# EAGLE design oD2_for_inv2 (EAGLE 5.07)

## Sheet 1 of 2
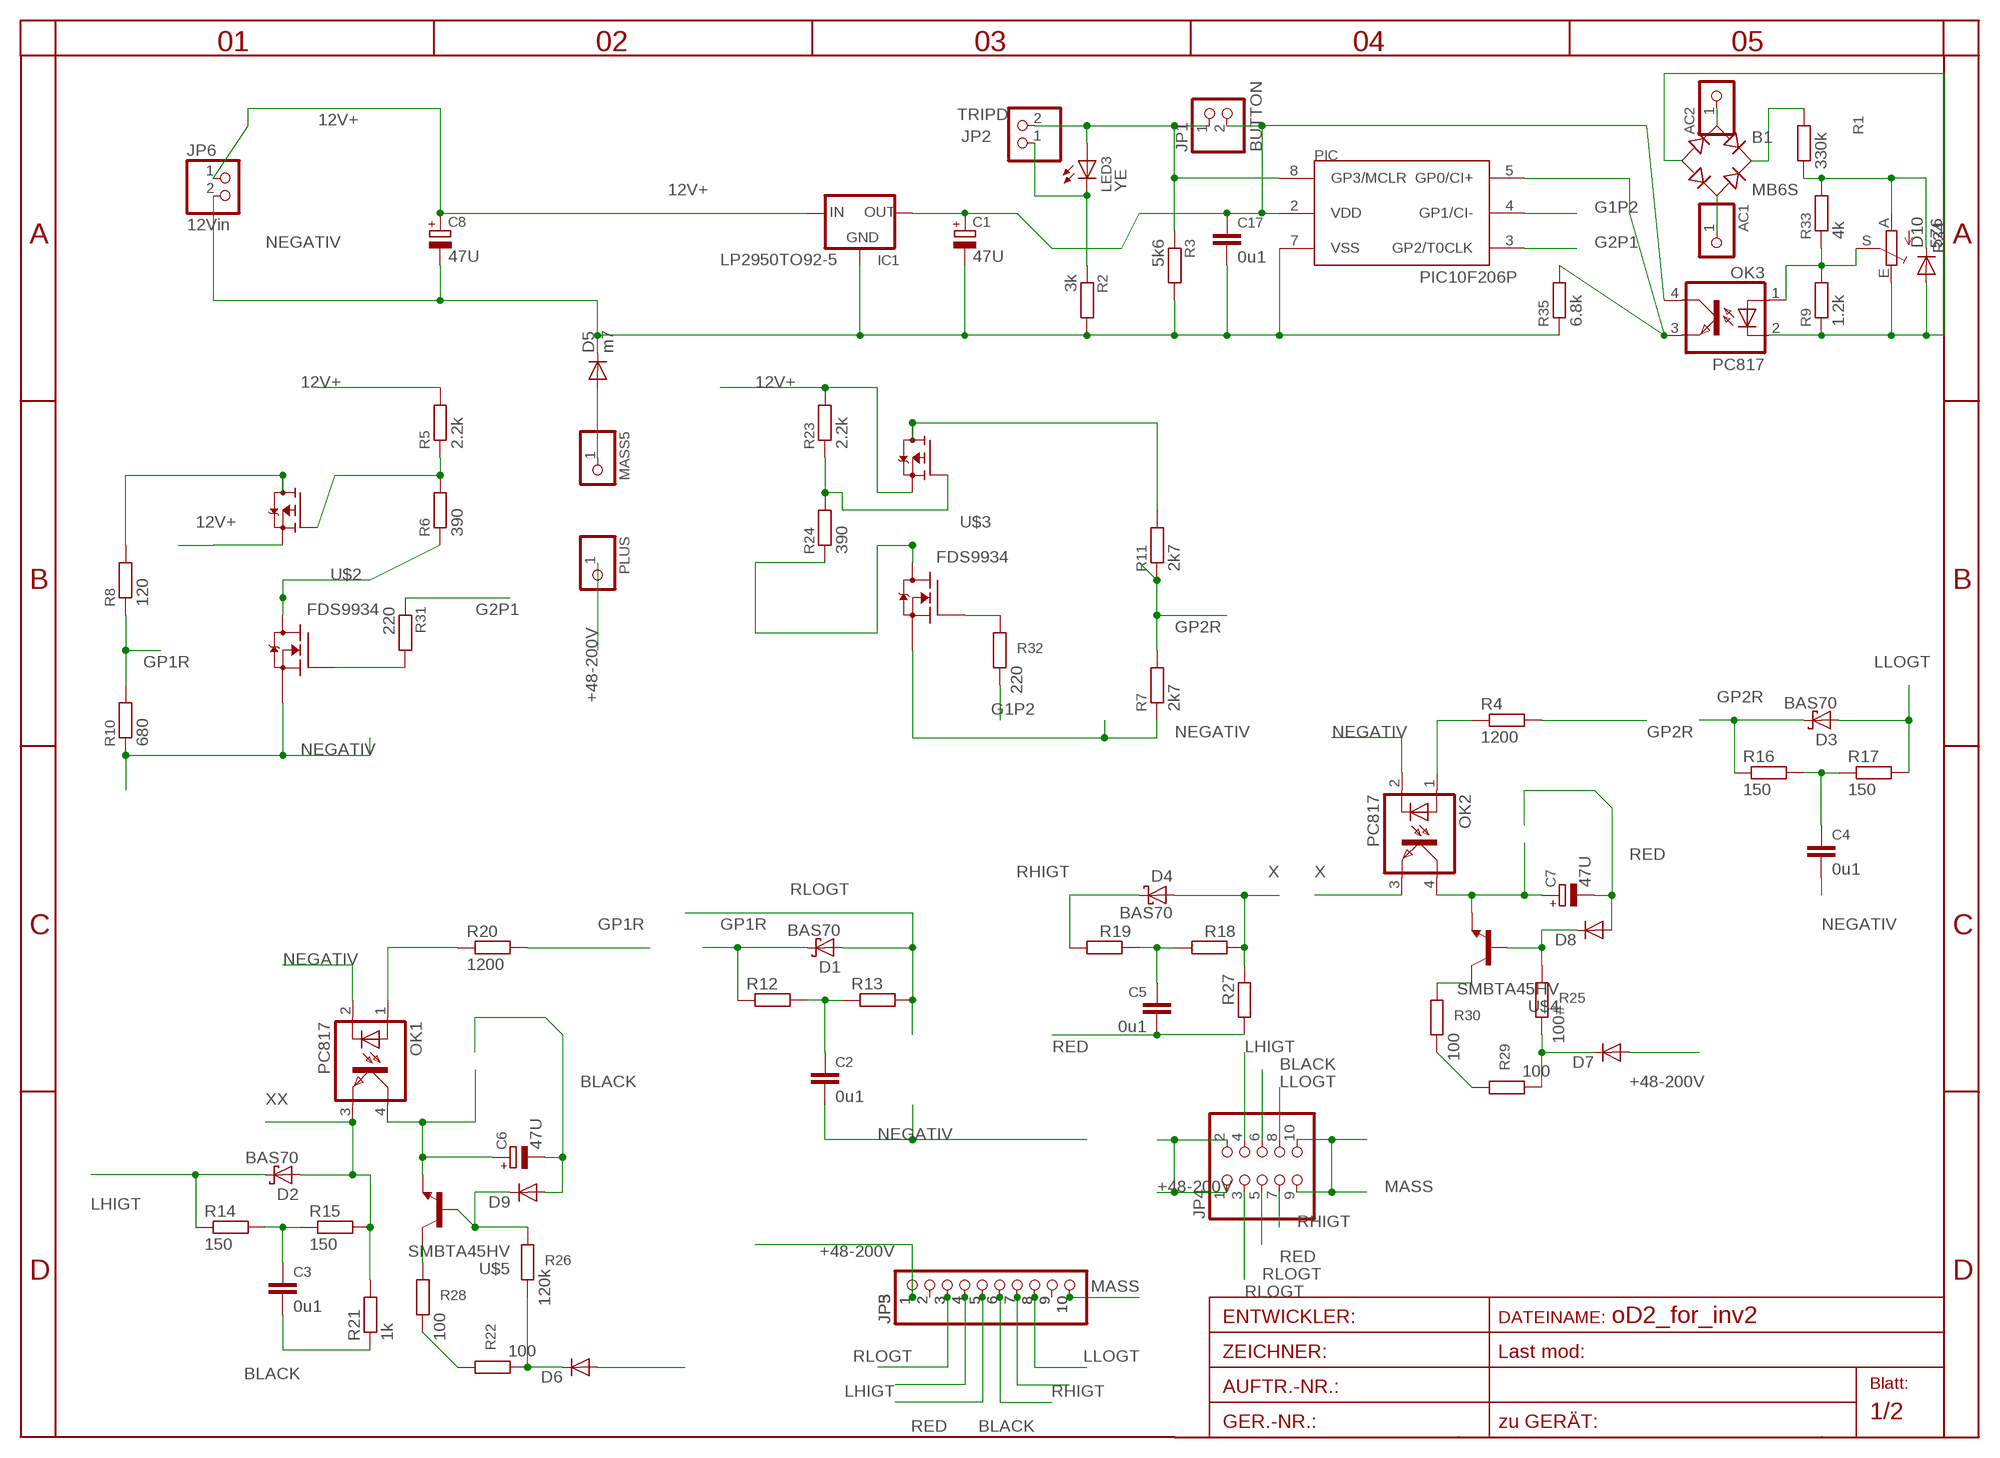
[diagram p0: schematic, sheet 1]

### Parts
AC1  PINHD-1X11MM6  [1X1MM8]
AC2  PINHD-1X11MM6  [1X1MM8]
B1  MB6S  [SOIC-4]
C1  47U  CPOL-EUE2.5-5  [E2,5-5]
C2  0u1  C-EUC1206  [C1206]
C3  0u1  C-EUC0805  [C0805]
C4  0u1  C-EUC1206  [C1206]
C5  0u1  C-EUC0805  [C0805]
C6  47U  CPOL-EUE2.5-6  [E2,5-6]
C7  47U  CPOL-EUE2.5-6  [E2,5-6]
C8  47U  CPOL-EUE2.5-7  [E2,5-7]
C17  0u1  C-EUC1206  [C1206]
D1  BAS70  [SOT23]
D2  BAS70  [SOT23]
D3  BAS70  [SOT23]
D4  BAS70  [SOT23]
D5  m7  DIODE-SMA-DO214  [SMA-DO214AC]
D6  DIODE-SMA-DO214  [SMA-DO214AC]
D7  DIODE-SMA-DO214  [SMA-DO214AC]
D8  DIODE-MINIMELF  [MINIMELF]
D9  DIODE-MINIMELF  [MINIMELF]
D10  5Z6  DIODE-MINIMELF  [MINIMELF]
IC1  LP2950TO92-5  [T092-5]
JP1  BUTTON  PINHD-1X2/90  [1X02/90]
JP2  TRIPD  PINHD-1X2/90  [1X02/90]
JP3  PINHD-1X10  [1X10WIDE]
JP4  PINHD-2X5  [2X05]
JP5  PINHD-1X10  [1X10WIDE]
JP6  12Vin  PINHD-1X2STR  [1X02]
LED3  YE  LEDCHIPLED_1206  [CHIPLED_1206]
MASS5  PINHD-1X11MM6  [1X1MM8]
OK1  PC817  [DIL04]
OK2  PC817  [DIL04]
OK3  PC817  [DIL04]
PIC  PIC10F206P  [DIL8]
PLUS  PINHD-1X11MM6  [1X1MM8]
R1  330k  R-EU_0204/5  [0204/5]
R2  3k  R-EU_R0805  [R0805]
R3  5k6  R-EU_R0805  [R0805]
R4  1200  R-EU_R1206  [R1206]
R5  2.2k  R-EU_R0805  [R0805]
R6  390  R-EU_R0805  [R0805]
R7  2k7  R-EU_R0805  [R0805]
R8  120  R-EU_R0805  [R0805]
R9  1.2k  R-EU_R0805  [R0805]
R10  680  R-EU_R0805  [R0805]
R11  2k7  R-EU_R0805  [R0805]
R12  R-EU_R0805  [R0805]
R13  R-EU_R0805  [R0805]
R14  150  R-EU_R0805  [R0805]
R15  150  R-EU_R0805  [R0805]
R16  150  R-EU_R0805  [R0805]
R17  150  R-EU_R0805  [R0805]
R18  R-EU_R0805  [R0805]
R19  R-EU_R0805  [R0805]
R20  1200  R-EU_R1206  [R1206]
R21  1k  R-EU_R0805  [R0805]
R22  100  R-EU_R1206  [R1206]
R23  2.2k  R-EU_R0805  [R0805]
R24  390  R-EU_R0805  [R0805]
R25  100#  R-EU_R1206  [R1206]
R26  120k  R-EU_R1206  [R1206]
R27  R-EU_R0805  [R0805]
R28  100  R-EU_R1206  [R1206]
R29  100  R-EU_R1206  [R1206]
R30  100  R-EU_R1206  [R1206]
R31  220  R-EU_R1206  [R1206]
R32  220  R-EU_R1206  [R1206]
R33  4k  R-EU_R0805  [R0805]
R34  TRIM_EU-S64W  [S64W]
R35  6.8k  R-EU_R0805  [R0805]
U$2  FDS9934  [SO-8]
U$3  FDS9934  [SO-8]
U$4  SMBTA45HV  [SOT23HV]
U$5  SMBTA45HV  [SOT23HV]

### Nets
12V+: C8.+ IC1.3(IN) JP6.1 R5.2 R23.2 U$2.3(Q2S) U$3.3(Q2S)
+48-200V: D6.A D7.A JP3.1 JP4.1 JP4.2 JP5.1 PLUS.1
BLACK: C3.2 C6.- D9.A JP3.6 JP4.6 JP5.6 R21.1
G1P2: PIC.4(GP1/CI-) R32.1
G2P1: PIC.3(GP2/T0CLK) R31.1
GP1R: D1.3(C) R8.1 R10.2 R12.1 R20.2
GP2R: D3.3(C) R4.2 R7.2 R11.1 R16.1
GP3: JP1.1 JP2.2 LED3.A PIC.8(GP3/MCLR) R3.1
LHIGT: D2.3(C) JP3.4 JP4.4 JP5.4 R14.1
LLOGT: D3.1(A) JP3.8 JP4.8 JP5.8 R17.2
MASS: D5.A JP3.10 JP4.9 JP4.10 JP5.10 MASS5.1 ; also sheet 2
N$1: OK3.3(EMIT) PIC.5(GP0/CI+) R35.2
N$2: R32.2 U$3.2(Q1G)
N$3: C3.1 R14.2 R15.1
N$4: R5.1 R6.2 U$2.4(Q2G)
N$5: R11.2 U$3.5(Q2D2) U$3.6(Q2D)
N$6: R31.2 U$2.2(Q1G)
N$7: C6.+ OK1.4(COL) U$5.2(E)
N$8: C5.1 R18.2 R19.1
N$9: R24.1 U$3.7(Q1D2) U$3.8(Q1D1)
N$11: R6.1 U$2.7(Q1D2) U$2.8(Q1D1)
N$12: C2.1 R12.2 R13.1
N$13: OK2.1(A) R4.1
N$14: C7.+ OK2.4(COL) U$4.2(E)
N$15: JP2.1 LED3.C R2.1
N$16: C4.1 R16.2 R17.1
N$17: OK1.1(A) R20.1
N$20: D7.K(C) R25.1 R29.1
N$21: R8.2 U$2.5(Q2D2) U$2.6(Q2D)
N$22: R23.1 R24.2 U$3.4(Q2G)
N$23: D6.K(C) R22.1 R26.1
N$24: R28.2 U$5.3(C)
N$25: JP3.2 JP5.2
N$26: R22.2 R28.1
N$27: D9.C R26.2 U$5.1(B)
N$28: R29.2 R30.1
N$31: D8.C R25.2 U$4.1(B)
N$33: R30.2 U$4.3(C)
N$34: JP3.9 JP5.9
N$35: OK3.1(A) R9.2 R33.1 R34.S
N$36: D10.C R1.1 R33.2 R34.A
N$37: B1.- D10.A OK3.2(C) R9.1 R34.E
N$38: AC1.1 B1.~2(AC2)
N$39: AC2.1 B1.~1(AC1)
N$40: B1.+ R1.2
NEGATIV: C1.- C2.2 C4.2 C8.- C17.2 D5.K(C) IC1.2(GND) JP6.2 OK1.2(C) OK2.2(C) PIC.7(VSS) R2.2 R3.2 R7.1 R10.1 R35.1 U$2.1(Q1S) U$3.1(Q1S)
RED: C5.2 C7.- D8.A JP3.5 JP4.5 JP5.5 R27.2
RHIGT: D4.3(C) JP3.7 JP4.7 JP5.7 R19.2
RLOGT: D1.1(A) JP3.3 JP4.3 JP5.3 R13.2
VDD: C1.+ C17.1 IC1.1(OUT) JP1.2 OK3.4(COL) PIC.2(VDD)
X: D4.1(A) OK2.3(EMIT) R18.1 R27.1
XX: D2.1(A) OK1.3(EMIT) R15.2 R21.2

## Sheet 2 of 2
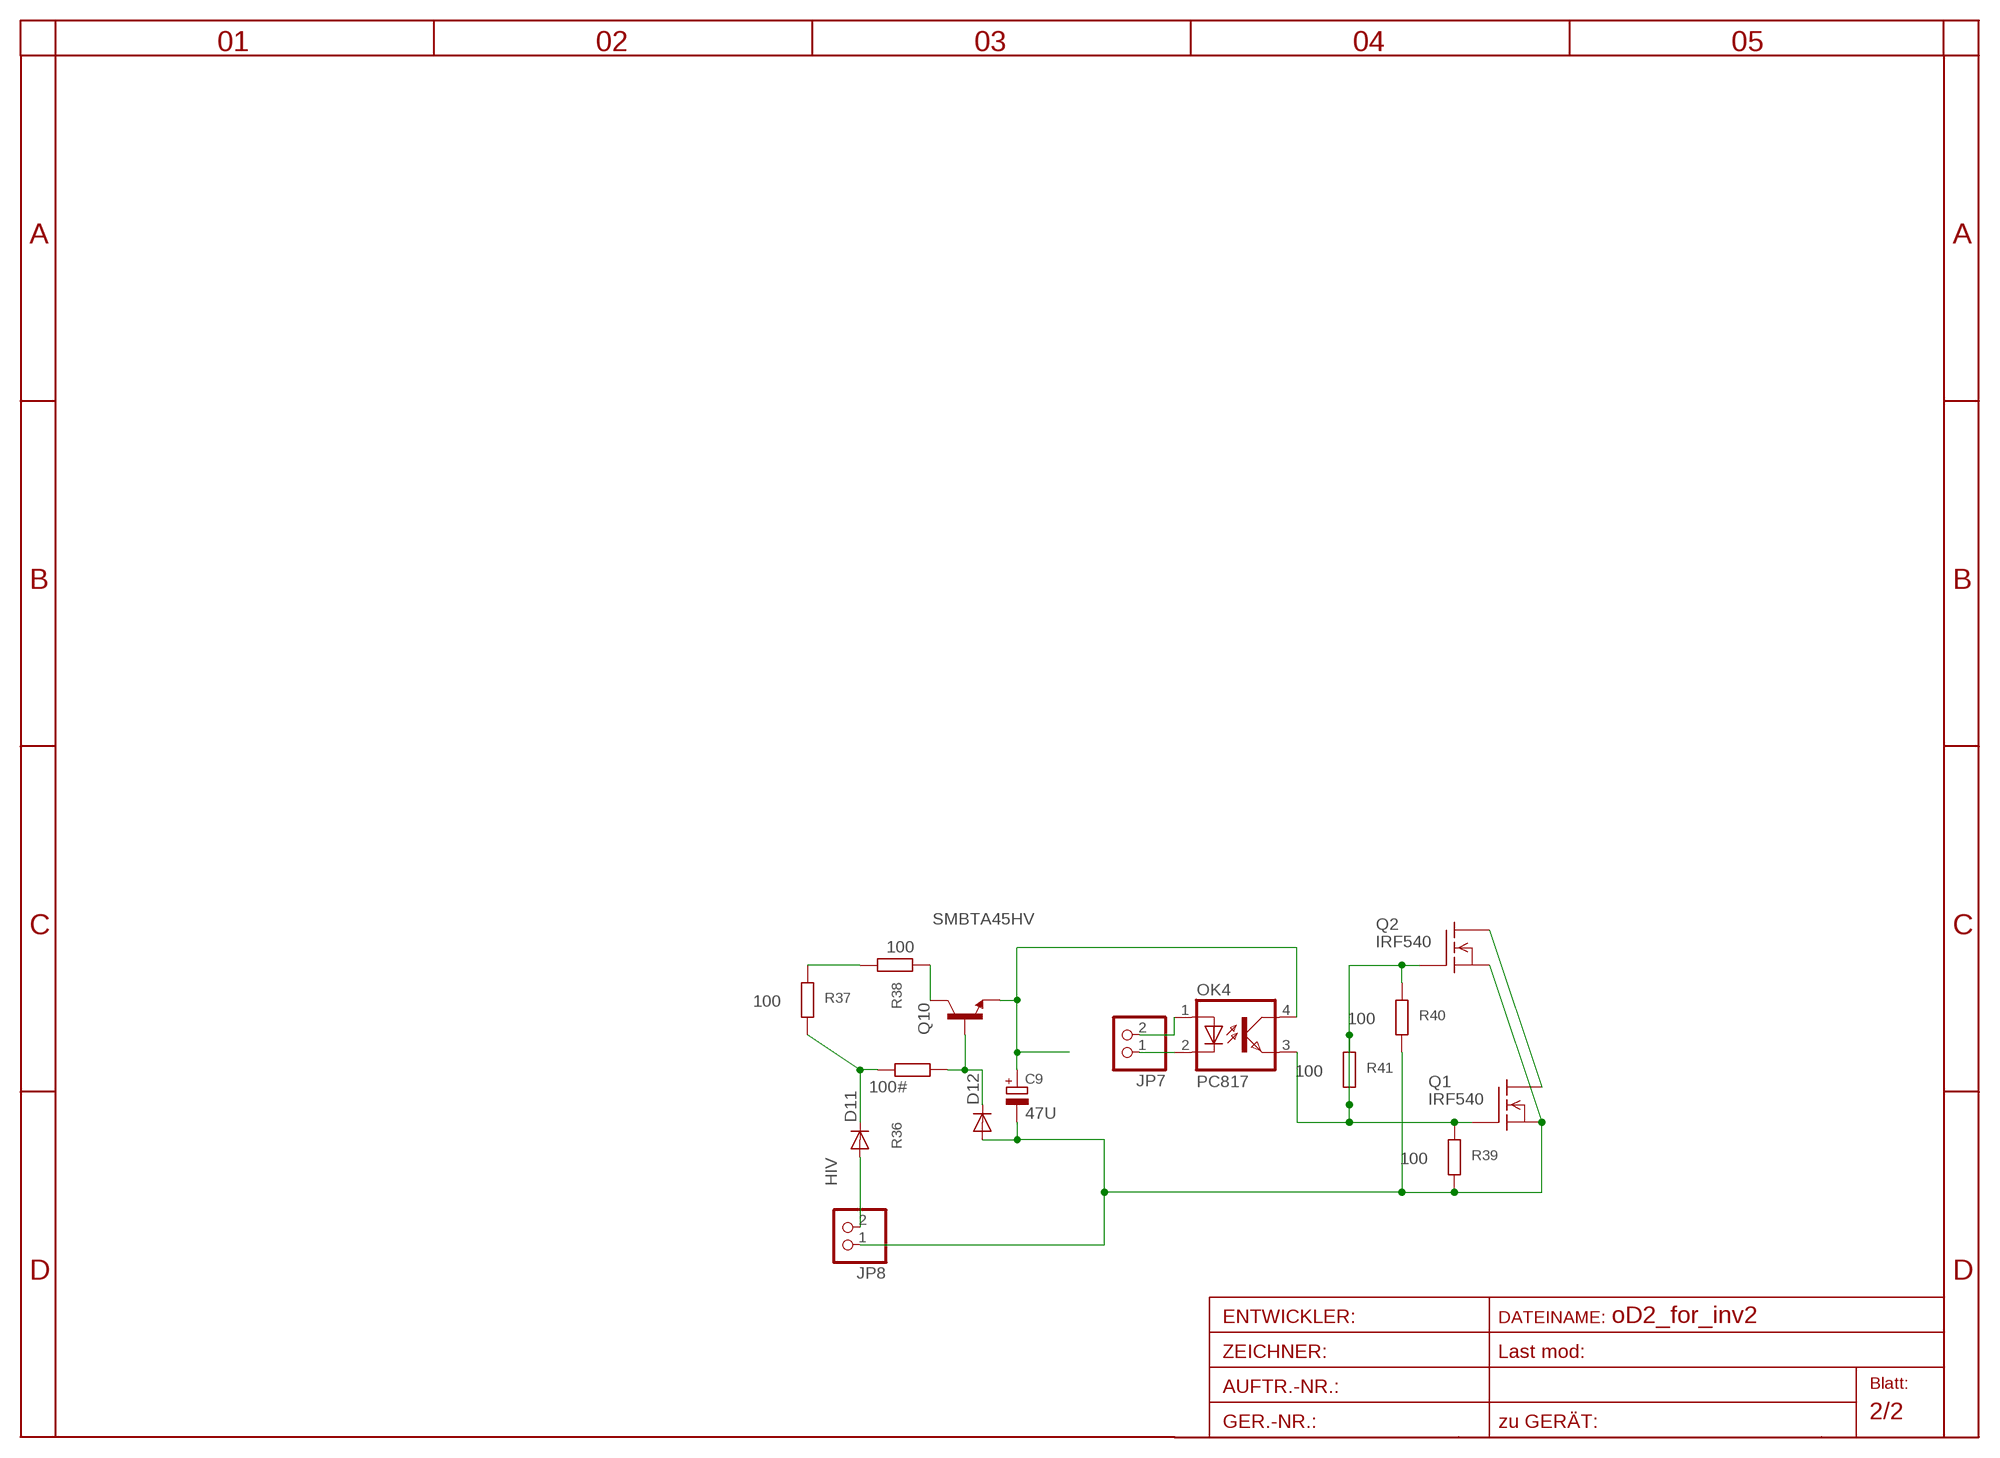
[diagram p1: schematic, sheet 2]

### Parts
C9  47U  CPOL-EUE2.5-6  [E2,5-6]
D11  DIODE-SMA-DO214  [SMA-DO214AC]
D12  DIODE-MINIMELF  [MINIMELF]
JP7  PINHD-1X2STR  [1X02]
JP8  PINHD-1X2STR  [1X02]
OK4  PC817  [DIL04]
Q1  IRF540  [TO220]
Q2  IRF540  [TO220]
Q10  SMBTA45HV  [SOT23HV]
R36  100#  R-EU_R1206  [R1206]
R37  100  R-EU_R1206  [R1206]
R38  100  R-EU_R1206  [R1206]
R39  100  R-EU_R1206  [R1206]
R40  100  R-EU_R1206  [R1206]
R41  100  R-EU_R1206  [R1206]

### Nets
HIV: D11.A JP8.2
MASS: Q1.2(D) Q2.2(D) ; also sheet 1
N$42: JP7.1 OK4.2(C)
N$43: OK4.3(EMIT) Q1.1(G) Q2.1(G) R39.2 R40.2 R41.1 R41.2
N$44: JP7.2 OK4.1(A)
N$48: C9.+ OK4.4(COL) Q10.2(E)
N$49: D11.K(C) R36.1 R37.1
N$50: R37.2 R38.1
N$51: D12.C Q10.1(B) R36.2
Q1: Q10.3(C) R38.2
XY: C9.- D12.A JP8.1 Q1.3(S) Q2.3(S) R39.1 R40.1

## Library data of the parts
AC1 AC2 MASS5 PLUS = pinhead:PINHD-1X1: PIN HEADER
B1 = rectifier:MB*S: Bridge Rectifier Source: http://www.fairchildsemi.com/ds/MB/MB6S.pdf
C1 C6-C9 = rcl-2:CPOL-EU: POLARIZED CAPACITOR, European symbol
C2-C5 C17 = rcl-2:C-EU: CAPACITOR, European symbol
D1-D4 = diode:BAS70: Silicon Schottky Diodes
D5-D12 = diode:DIODE-: DIODE
IC1 = v-reg:LP2950?*: Source: http://cache.national.com/ds/LP/LP2950.pdf
JP1 JP2 JP6-JP8 = pinhead:PINHD-1X2: PIN HEADER
JP3 JP5 = pinhead:PINHD-1X10: PIN HEADER
JP4 = pinhead:PINHD-2X5: PIN HEADER
LED3 = led:LED: LED
OK1-OK4 = optocoupler:PC817: SHARP OPTO COUPLER
PIC = microchip-5:PIC10F2*: uPC nW 0,25/0,5k Program Flash memory Comparator
Q1 Q2 = transistor-fet:IRF540: N-Channel Enhancement MOSFET (HEXFET); 100V; 28A; 0,077Ohm
Q10 U$4 U$5 = transistor-npn:SMBTA45
R1-R3 R5-R11 R22-R26 R28-R33 R35-R41 = rcl-2:R-EU_: RESISTOR, European symbol
R4 R12-R21 R27 = rcl:R-EU_: RESISTOR, European symbol
R34 = pot:TRIM_EU-: POTENTIOMETER
U$2 U$3 = transistor-fet:FDS9934

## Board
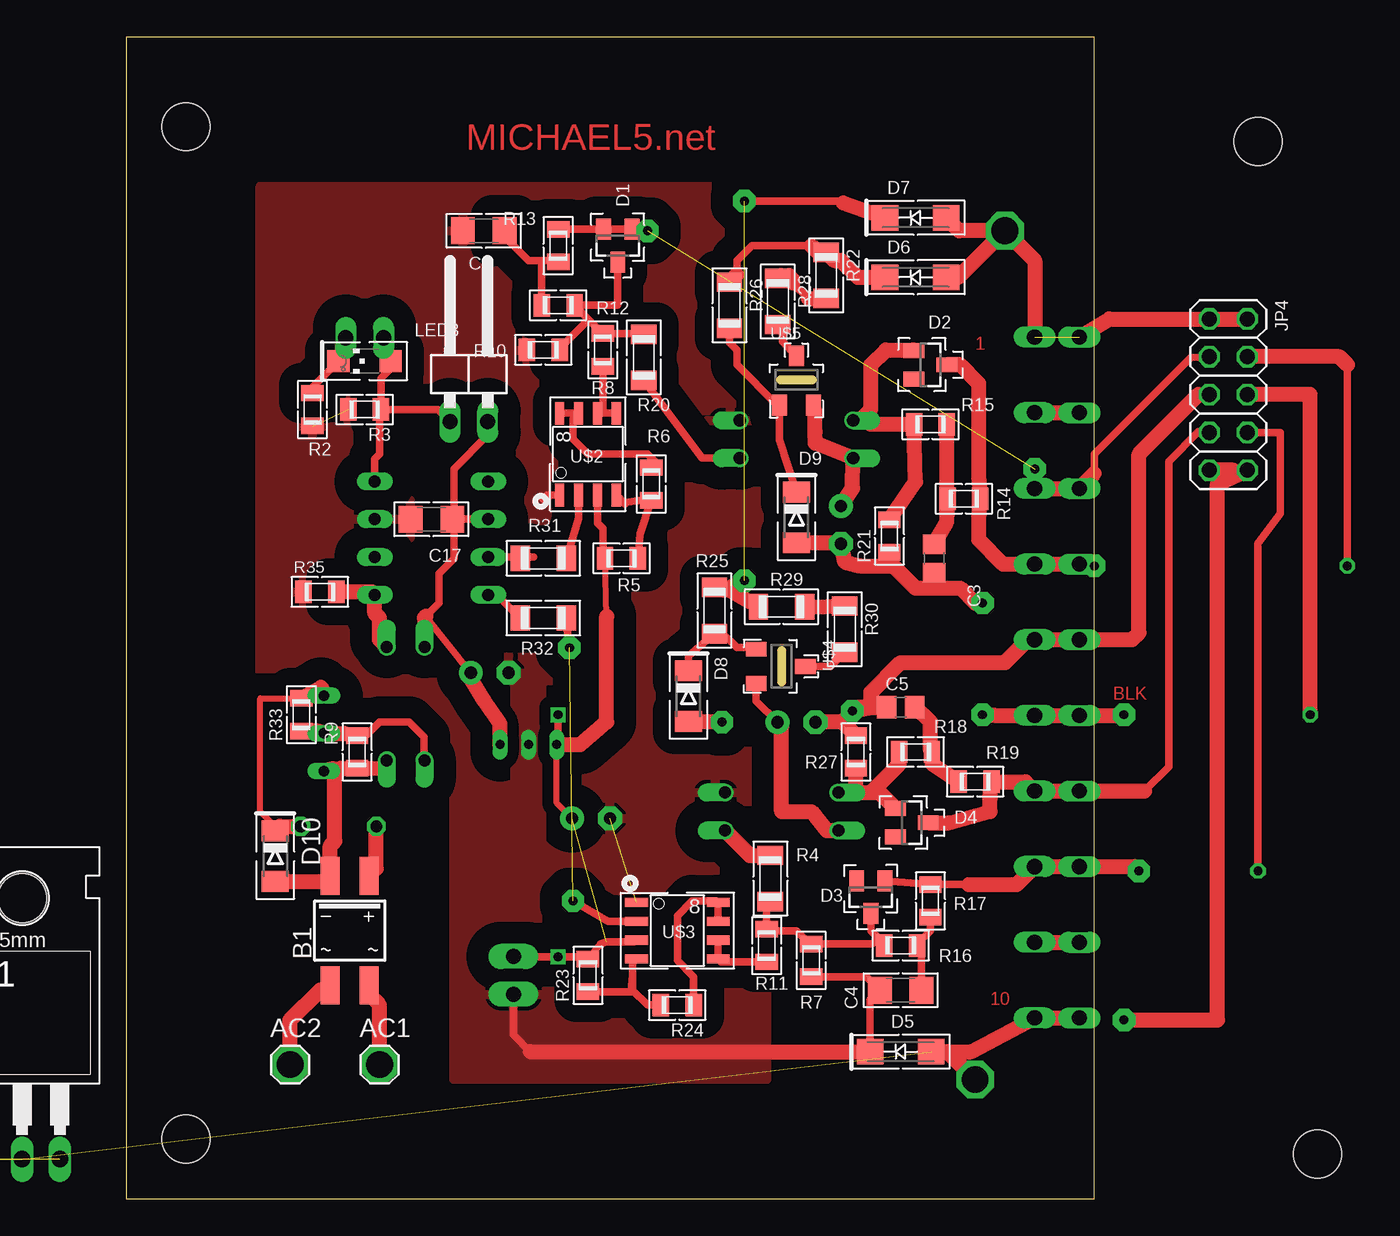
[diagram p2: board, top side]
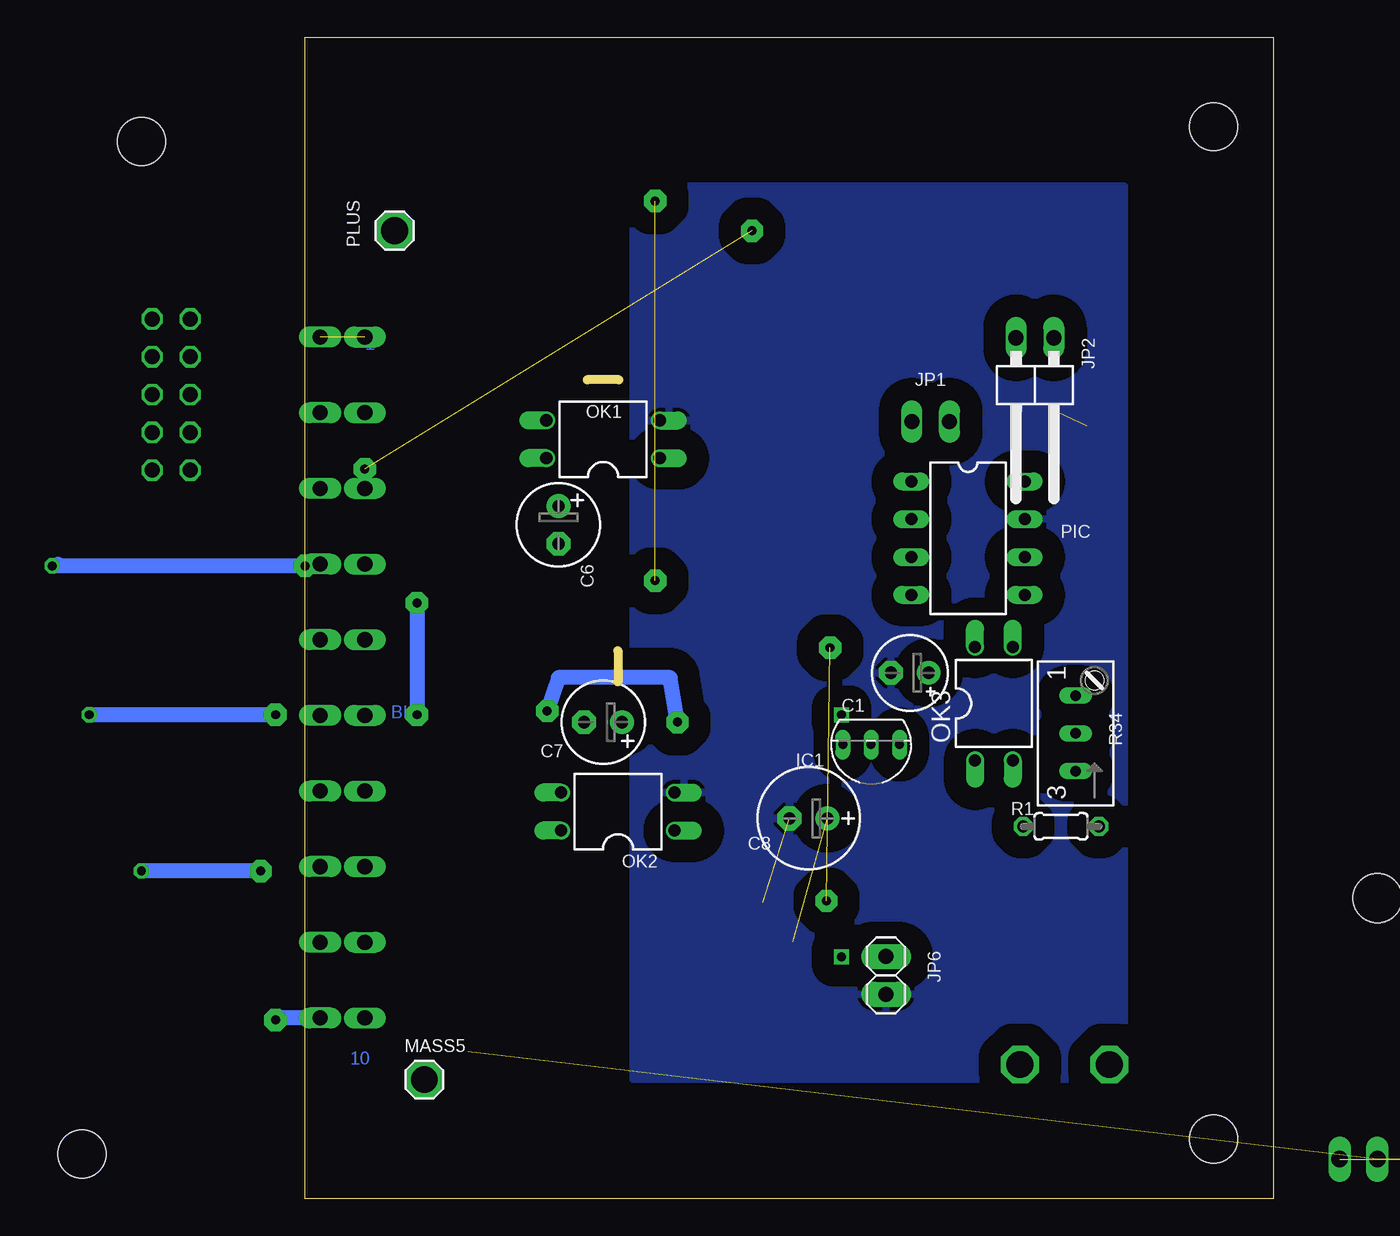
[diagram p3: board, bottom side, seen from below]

Size 65 x 78 mm. Coordinates in mm from the lower left corner, seen from the top.
Outline: 0,0 65,0 65,78 0,78 0,0
Copper layers (1*16): Top 0.035mm / dielectric 1.5mm / Bottom 0.035mm
Design rules "default *": minimum track width 12mil, minimum drill 24mil, track to track 8mil, track to pad 8mil, pad to pad 8mil, via to via 8mil, smd to smd 8mil, copper to edge 40mil, drill to drill 8mil, minimum pad ring 8mil, minimum via ring 8mil, stop-mask expansion 4mil, vias tented up to drill 0mil, thermal gap 10mil
Holes 3.2 mm at 4,72 4,4 76,71 80,3

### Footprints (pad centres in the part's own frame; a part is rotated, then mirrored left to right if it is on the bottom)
1X1MM8 = drill 1.8 pad 2.54 octagon: 1 0,0
SOIC-4 = smd 1.27 x 2.54: + 1.3,3.685; - -1.3,3.685; ~1 -1.3,-3.685; ~2 1.3,-3.685
E2,5-5 = drill 0.813 pad 1.6 round: + -1.27,0 | drill 0.813 pad 1.6 octagon: - 1.27,0
C1206 = smd 1.6 x 1.8: 1 -1.4,0; 2 1.4,0
C0805 = smd 1.3 x 1.5: 1 -0.95,0; 2 0.95,0
E2,5-6 = drill 0.813 pad 1.6 round: + -1.27,0 | drill 0.813 pad 1.6 octagon: - 1.27,0
E2,5-7 = drill 0.813 pad 1.6 round: + -1.27,0 | drill 0.813 pad 1.6 octagon: - 1.27,0
SOT23 = smd 1 x 1.4: 1 -0.95,-1.1; 2 0.95,-1.1; 3 0,1.1
SMA-DO214AC = smd 1.8 x 1.7: A 2.05,-0.127; K -2.05,-0.127
MINIMELF = smd 1.4 x 1.8: A 1.7,0; C -1.7,0
T092-5 = drill 0.6 pad 0.813 long: 1 -1.905,0; 2 0,0; 3 1.905,0
1X02/90 = drill 1.016 long: 1 -1.27,-3.81; 2 1.27,-3.81
1X10WIDE = drill 1.016 long: 1 -22.86,0; 2 -17.78,0; 3 -12.7,0; 4 -7.62,0; 5 -2.54,0; 6 2.54,0; 7 7.62,0; 8 12.7,0; 9 17.78,0; 10 22.86,0
2X05 = drill 1.016 octagon: 1 -5.08,-1.27; 2 -5.08,1.27; 3 -2.54,-1.27; 4 -2.54,1.27; 5 0,-1.27; 6 0,1.27; 7 2.54,-1.27; 8 2.54,1.27; 9 5.08,-1.27; 10 5.08,1.27
1X02 = drill 1.016 pad 1.676 long: 1 -1.27,0; 2 1.27,0
CHIPLED_1206 = smd 1.5 x 1.5: A 0,-1.75; C 0,1.75
DIL04 = drill 0.813 offset: 1 -1.27,-3.81; 2 1.27,-3.81; 3 1.27,3.81; 4 -1.27,3.81
DIL8 = drill 0.8 long: 1 -3.81,-3.81; 2 -1.27,-3.81; 3 1.27,-3.81; 4 3.81,-3.81; 5 3.81,3.81; 6 1.27,3.81; 7 -1.27,3.81; 8 -3.81,3.81
TO220 = drill 1.118 long: 1 -2.54,-6.35; 2 0,-6.35; 3 2.54,-6.35 | hole 3.302: 0,11.176
SOT23HV = smd 1 x 1.4: 1 -1.15,-1.7; 2 1.15,-1.7; 3 0,1.6
0204/5 = drill 0.8 pad 1.27 octagon: 1 -2.54,0; 2 2.54,0
R0805 = smd 1.1 x 1.5: 1 -1.1,0; 2 1.1,0
R1206 = smd 1.3 x 1.7: 1 -1.55,0; 2 1.55,0
S64W = drill 0.7 long: A 2.54,1.27; E -2.54,1.27; S 0,1.27
SO-8 = smd 1.524 x 0.61: 1 -2.743,1.905; 2 -2.743,0.635; 3 -2.743,-0.635; 4 -2.743,-1.905; 5 2.743,-1.905; 6 2.743,-0.635; 7 2.743,0.635; 8 2.743,1.905

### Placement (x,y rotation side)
AC1  17,9 0 top
AC2  11,9 0 top
B1  15,18 0 top
C1  24.4,35.32 180 bottom
C2  24,65 180 top
C3  54.25,43 270 top
C4  52,14 180 top
C5  52,33 180 top
C6  48,45.25 270 bottom
C7  45,32 180 bottom
C8  31.2,25.55 180 bottom
C9  not placed on the board
C17  20.49,45.63 180 top
D1  33,64 180 top
D2  54,56 270 top
D3  50,20.25 180 top
D4  52.75,25.25 270 top
D5  52,10 0 top
D6  53,62 0 top
D7  53,66 0 top
D8  37.75,33.75 270 top
D9  45,45.75 270 top
D10  10,23 270 top
D11  not placed on the board
D12  not placed on the board
IC1  27,30.5 180 bottom
JP1  23,56 0 top
JP2  16,54 180 bottom
JP3  61,35 270 bottom
JP4  74,54 270 top  (outside the outline)
JP5  64,35 270 top
JP6  26,15 270 bottom
JP7  not placed on the board
JP8  not placed on the board
LED3  16,56.25 90 top
MASS5  57,8 0 bottom
OK1  45,51 90 bottom
OK2  44,26 90 bottom
OK3  18.75,33.25 0 bottom
OK4  not placed on the board
PIC  20.49,44.36 270 bottom
PLUS  59,65 180 bottom
Q1  not placed on the board
Q2  not placed on the board
Q10  not placed on the board
R1  14.25,25 180 bottom
R2  12.5,53 270 top
R3  16,53 180 top
R4  43.25,21.5 270 top
R5  33.25,43 180 top
R6  35.25,48 270 top
R7  46,16 90 top
R8  32,57 270 top
R9  15.5,30 90 top
R10  28,57 0 top
R11  43,17 270 top
R12  29,60 180 top
R13  29,64 90 top
R14  56.25,47 180 top
R15  54,52 180 top
R16  52,17 0 top
R17  54,20 90 top
R18  53,30 0 top
R19  57,28 0 top
R20  34.75,56.5 90 top
R21  51.25,44.5 90 top
R22  47,62 270 top
R23  31,15 90 top
R24  37,13 180 top
R25  39.5,39.5 270 top
R26  40.5,60 270 top
R27  49,30 90 top
R28  43.75,60.25 270 top
R29  44,39.75 0 top
R30  48.25,38.25 270 top
R31  28,43 0 top
R32  28,39 0 top
R33  11.75,32.5 90 top
R34  12,31.25 90 bottom
R35  13,40.75 0 top
R36  not placed on the board
R37  not placed on the board
R38  not placed on the board
R39  not placed on the board
R40  not placed on the board
R41  not placed on the board
U$2  31,50 90 top
U$3  37,18 0 top
U$4  44,35.75 270 top
U$5  45,55 0 top

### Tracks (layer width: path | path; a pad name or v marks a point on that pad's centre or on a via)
12V+  (via drill 0.6)  (1 unrouted)
  Top 0.406: 32.25,39.1 R5.2 | IC1.3 28.91,26.57 C8.+
  Top 0.5: 27.08,16.1 JP6.1 26.02,16.25 v29,16.25 30.85,16.25 R23.2 31.85,17.1 32.25,17.25 34.12,17.25 U$3.3 | U$2.3 31.63,45.37 32,45 32,43.15 R5.2 | v29,32.5 29,30.59 IC1.3
  Top 1: IC1.3 30.5,30.5 32.25,32 32.25,39.1
+48-200V  (1 unrouted)
  Top 1: JP5.1 66,59.08 JP4.1 JP4.2 | JP3.1 61,63 PLUS.1 | PLUS.1 55.92,65 D7.A | D6.A 55.87,61.87 PLUS.1
BLACK  (via drill 0.6 pad 1.02, 0.6 pad 1.5)
  Top 0.406: 51,42.5 R21.1
  Top 1: JP4.6 79.5,54 v79.5,32.5 | v67,32.5 66.96,32.46 JP5.6 JP3.6 58.29,32.46 v57.5,32.5 | v57.5,40 57,40 56,41 54,41 | C6.- 48.23,42.77 49.25,42.5 51,42.5 51.5,42.5 53,41 54,41 | C3.2 54.25,41.25 54,41
  Top 1.016: D9.A 47.68,44.05 C6.-
  Bottom 1: v67,32.5 v79.5,32.5 | v57.5,40 v57.5,32.5
G1P2
  Top 0.5: PIC.4 24.9,40.55 R32.1
G2P1
  Top 0.5: PIC.3 27.36,43.09 R31.1
GP1R
  Top 0.5: R20.2 34.25,58.1 R8.1 31.05,59.05 | 31.05,59.05 R12.1 33,60 D1.3 | R10.2 29.1,57.1 31.05,59.05
GP2R
  Top 0.5: R16.1 50.9,17.1 50.5,17.5 | 50.5,17.5 50,18 D3.3 | 50.5,17.5 50.1,17.1 R7.2 45.9,17.1 45,18 43.1,18 R11.1 43,19.7 R4.2
GP3
  Top 0.5: PIC.8 16.68,49.68 17,50 17,52.9 R3.1 | R3.1 17.1,55.1 18,56 LED3.A 17.75,57.33 JP2.2 | R3.1 20.92,53 JP1.1
HIV  (1 unrouted)
LHIGT  (via drill 0.6 pad 1.02, 0.6 pad 1.5)
  Top 0.5: v82,42.5 82,56
  Top 1: JP4.4 81.46,56.54 82,56 | v65,42.5 64.88,42.62 JP5.4 JP3.4 58.88,42.62 57.25,44.25 57.25,45.65 R14.1 57.35,47.4 57.25,48.5 57.25,54.75 56,56 D2.3
  Bottom 1: 81.62,42.62 v82,42.5 v65,42.5
LLOGT  (via drill 0.6 pad 1.02, 0.6 pad 1.5)
  Top 0.5: D3.1 R17.2 56.55,21.1 | JP4.8 77.5,51.46 77.5,46 76,44 v76,22
  Top 1: v68,22 67.7,22.3 JP5.8 JP3.8 59.8,21.1 56.55,21.1
  Bottom 1: v68,22 v76,22
MASS  (via drill 0.6 pad 1.5)  (2 unrouted)
  Top 0.5: D5.A 55.13,9.87
  Top 1: MASS5.1 55.13,9.87 56.73,9.87 JP3.10 JP5.10 | v67,12 73.27,12 73.27,48 | 73.27,48 JP4.10 | JP4.9 74.35,48.92 73.27,48
  Bottom 1: JP5.10 67,12.14 v67,12
N$1
  Top 1: R35.2 16.48,40.75 PIC.5 16.68,39.32 17,39 17,37.54 OK3.3
N$2  (via drill 0.6 pad 1.5)  (1 unrouted)
  Top 0.5: U$3.2 32.37,18.64 v30,20 | R32.2 29.55,38.45 v29.75,37
N$3
  Top 1: R15.1 55.1,45.8 R14.2 55.1,45.45 C3.1
N$4
  Top 0.5: R5.1 34.5,44.65 R6.2 34.35,46.9 33.5,46.75 33.5,46.66 U$2.4
N$5
  Top 0.5: R11.2 39.94,15.9 U$3.5 U$3.6
N$6
  Top 0.5: U$2.2 30.37,45.69 R31.2
N$7
  Top 0.5: U$5.2 46.15,52.95 46.25,52.85
  Top 1: 46.25,52.85 46.25,51.5 46.27,50.73 OK1.4 48.77,47.69 C6.+
N$8
  Top 1: R19.1 54.1,29.2 R18.2 54,30.1 54,32 53,33 C5.1
N$9
  Top 0.5: R24.1 38.1,14.9 37,16 37,19 38,20 39.65,20 U$3.8 U$3.7
N$11
  Top 0.5: R6.1 35.5,49.5 35,50 31,50 30,51 30,52.38 U$2.7 U$2.8
N$12
  Top 0.5: C2.1 25.4,64.6 27,63 28,63 | 28,63 28.9,63 R13.1 | R12.2 27.9,62.9 28,63
N$13
  Top 1: R4.1 41.87,23.05 OK2.1
N$14
  Top 0.5: U$4.2 42.3,33.43 C7.+
  Top 1: OK2.4 47.02,24.73 46,26 44,26 44,31.73 C7.+
N$15
  Top 0.5: R2.1 12.5,54.5 LED3.C 14.25,57.33 JP2.1
N$16
  Top 0.5: C4.1 53.4,16.7 R16.2 53.1,17.1 54,18 R17.1
N$17
  Top 0.5: OK1.1 38.67,49.73 R20.1
N$20  (via drill 0.6 pad 1.5)  (1 unrouted)
  Top 0.5: v41.5,67 48,67 48.13,66.87
  Top 1: 48.13,66.87 D7.K | 40.15,41.05 R25.1 | R29.1 40.15,41.05 | 40.15,41.05 40.15,40.85 v41.5,41.5
N$21
  Top 0.5: U$2.6 31.74,52.74 | 31.74,52.74 U$2.5 | 31.74,52.74 32,53 R8.2
N$22
  Top 0.5: R24.2 35,13 34,14 34,15 | 34,15 34,15.84 U$3.4 | R23.1 33.9,13.9 34,15
N$23
  Top 0.5: 46,64 42,64 41,63 41,62.05
  Top 1: 46,64 46.45,63.55 R22.1 47.55,63 48,63 49.13,61.87 D6.K | R26.1 41,62.05
N$24
  Top 0.5: 44.05,58.7 44.05,57.55 U$5.3
  Top 1: 44.05,58.7 R28.2
N$25
  Top 1.016: JP3.2 JP5.2
N$26
  Top 0.5: 44.75,61.5 45.8,60.45 | 44.5,62 44.75,61.75
  Top 1: 45.8,60.45 R22.2 | 44.75,61.75 44.75,61.5 | 44.5,62 43.95,62 R28.1
N$27
  Top 0.5: R26.2 40.5,57.5 41,57 41,56 43.7,53.3 U$5.1 43.85,50.95 D9.C
N$28
  Top 1: R29.2 45.7,39.75 R30.1
N$31
  Top 0.5: D8.C 37.75,36.45 R25.2 40.05,37.95 41,37 42.2,37 U$4.1
N$33
  Top 0.5: U$4.3 47.3,35.75 R30.2
N$34
  Top 1: JP3.9 JP5.9
N$35
  Top 0.5: R9.2 16.1,31.1 17,32 19,32 20,31 20,29.46 OK3.1
  Top 1: R33.1 12.87,31.4 R34.S 14.6,31.25 R9.2
N$36
  Top 0.406: R33.2 9,33.6 9,26 10,25 D10.C
  Top 1: R1.1 10.3,25 D10.C | R33.2 13.08,34.35 R34.A
N$37
  Top 1: D10.A 13.32,21.3 B1.- 13.7,23.7 14,24 14,28.73 13.86,28.87 | 13.86,28.87 R34.E | OK3.2 17.46,28.94 R9.1 14.4,28.9 13.86,28.87
N$38
  Top 1: B1.~2 16.3,13.7 17,13 AC1.1
N$39
  Top 1: AC2.1 11,12 13,14 13.39,14 B1.~1
N$40
  Top 1: R1.2 16.79,22.18 B1.+
N$42  (1 unrouted)
N$43  (6 unrouted)
N$44  (1 unrouted)
N$48  (2 unrouted)
N$49  (2 unrouted)
N$50  (1 unrouted)
N$51  (2 unrouted)
NEGATIV  (2 unrouted)
  Top 0.5: 27.13,9.87 26,11 JP6.2 | D5.K 49.95,13.35 C4.2 49.7,14.9 R7.1 | U$2.1 28.26,47.26 28,47
  Top 1: 27.13,9.87 D5.K
  pour Top (isolate 1.5, rank 4): 9,68 43,68 43,8 22,8 22,27 9,27
  pour Bottom (isolate 1.5): 10,68 43,68 43,8 10,8
  pour Top (isolate 0.75, no thermals): 26,35 28,35 28,24 26,24
Q1  (1 unrouted)
RED  (via drill 0.6 pad 1.5)
  Top 1: JP4.5 72,54 68,50 68,38 67.54,37.54 JP5.5 JP3.5 60.54,37.54 59,36 52,36 50,34 50,33 | 48.1,32 C7.- | 48.1,32 R27.2 | 50,33 49.1,33 48.1,32 | 50,33 C5.2 | D8.A 39.95,32.05 v40,32 | v48.75,32.75 50,33
  Bottom 1: v40,32 40.5,35 48,35 v48.75,32.75
RHIGT
  Top 0.5: 68.38,27.38 70,29 70,49.5 72,51.5 JP4.7
  Top 1: 68.38,27.38 JP5.7 JP3.7 | D4.3 55.25,25.25 58,26 58,26.9 R19.2
  Top 1.016: R19.2 60.38,28 JP3.7
RLOGT  (via drill 0.6 pad 1.5)  (1 unrouted)
  Top 0.5: R13.2 D1.1 | JP4.3 71.5,56.5 65,50 65,48.7
  Top 1: 65,48.7 JP5.3 JP3.3 v61,49 | D1.1 34.9,65.1 v35,65
VDD
  Top 0.5: C1.+ 20.11,39.11 21,40 21,42 22,43 22,45.52 C17.1 | C17.1 PIC.2 | JP1.2 24.27,51.27 22,49 22,45.74 C17.1
  Top 1: OK3.4 20.02,39.02 20.11,39.11 | IC1.1 25.09,31.91 24,33.5 23,35.19 C1.+
X
  Top 1: OK2.3 49,27.27 | 49,27.27 50,27.27 | 50,27.27 50.58,27.27 D4.1 | R18.1 51.9,29.17 50,27.27 | 49,27.27 R27.1
XX
  Top 1: OK1.3 49.27,52.27 49.5,52.5 | 49.5,52.5 50,53 50,56 51,57 52.85,57 D2.1 | 49.5,52.5 50,52 R15.2 53,48.15 R21.2
XY  (6 unrouted)

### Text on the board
Top: MICHAEL5.net | 1 | BLK | 10
Bottom: 1 | BLK | 10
